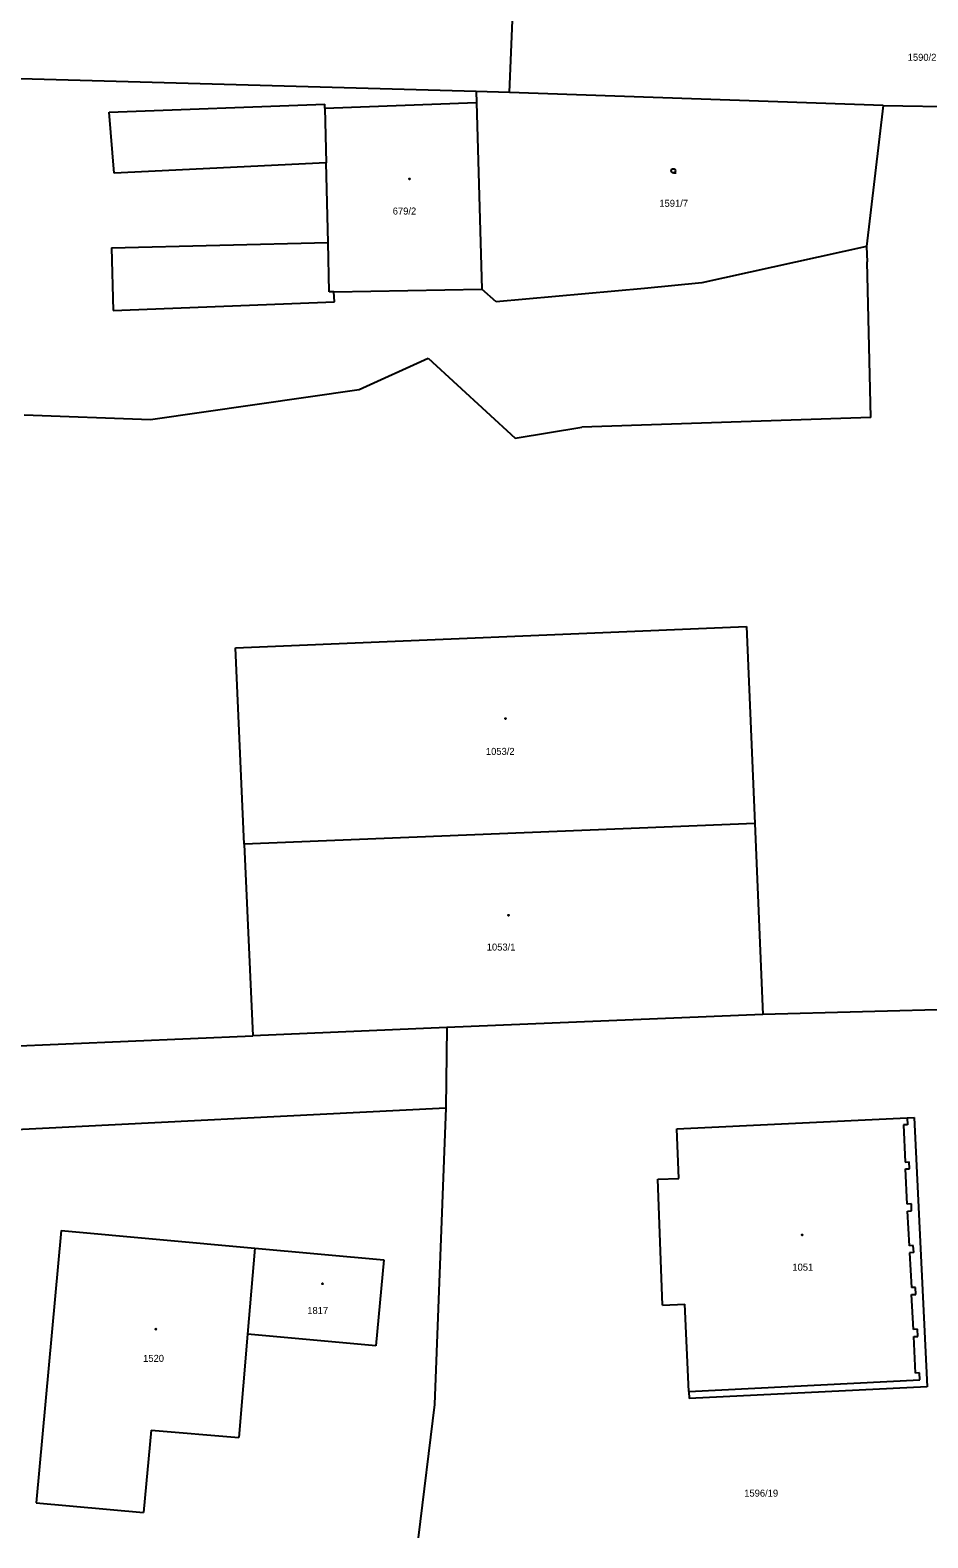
# Model space of a CAD drawing. Extents: x -866624 to -866276, y -1050208 to -1049940.
# Drawn here: x -866393.3 to -866329.4, y -1050208.1 to -1050100.7 of the extents above; entities that cross this region are included whole.
import ezdxf

# ---------------------------------------------------------------- set-up
doc = ezdxf.new("R2010")
doc.units = 0
for name, color, linetype in [('Default', 7, 'Continuous'), ('Hranice', 7, 'Continuous'), ('Hranice další', 7, 'Continuous'), ('Hranice-budov', 7, 'Continuous'), ('Parcela-pozemkova', 7, 'Continuous'), ('Parcela-stavebni', 7, 'Continuous'), ('znacky-budov', 7, 'Continuous'), ('Znacky-kultury', 7, 'Continuous')]:
    doc.layers.add(name, color=color, linetype=linetype)

# ---------------------------------------------------------------- blocks, each defined once
blk = doc.blocks.new('p_zahr')
at = {"layer": 'Default'}
blk.add_line((0, -0.75), (0.99, -0.75), dxfattribs=at)
blk.add_circle((0, 0), 0.75, dxfattribs=at)
blk = doc.blocks.new('s_zdena')
at = {"layer": 'Default'}
blk.add_circle((0, 0), 0.175, dxfattribs=at)
for start, end in [(0, 180), (180, 0)]:
    blk.add_arc((0, 0), 0.0875, start, end, dxfattribs=at)

msp = doc.modelspace()

# ---------------------------------------------------------------- linework, layer by layer
at = {"layer": 'Hranice'}
for p, q in [((-866359.18, -1050105.1), (-866358.8, -1050095.64)), ((-866361.55, -1050105.03), (-866399.74, -1050103.97)), ((-866359.18, -1050105.1), (-866361.55, -1050105.03)), ((-866361.55, -1050105.03), (-866361.53, -1050105.82)), ((-866332.54, -1050106.03), (-866359.18, -1050105.1)), ((-866387.7, -1050106.5), (-866372.34, -1050105.95)), ((-866387.36, -1050110.85), (-866387.7, -1050106.5)), ((-866372.33, -1050106.22), (-866372.34, -1050105.95)), ((-866372.33, -1050106.22), (-866361.53, -1050105.82)), ((-866361.53, -1050105.82), (-866361.15, -1050119.13)), ((-866332.54, -1050106.03), (-866333.74, -1050116.1)), ((-866332.54, -1050106.03), (-866295.74, -1050106.73)), ((-866372.25, -1050110.12), (-866387.36, -1050110.85)), ((-866372.11, -1050115.81), (-866372.25, -1050110.12)), ((-866387.54, -1050116.19), (-866372.11, -1050115.81)), ((-866387.54, -1050116.19), (-866387.43, -1050120.65)), ((-866333.74, -1050116.1), (-866345.48, -1050118.69)), ((-866333.74, -1050116.1), (-866333.7, -1050117.18)), ((-866333.42, -1050128.28), (-866333.7, -1050117.18)), ((-866371.69, -1050119.32), (-866361.15, -1050119.13)), ((-866371.66, -1050120.04), (-866371.69, -1050119.32)), ((-866360.13, -1050120.04), (-866361.15, -1050119.13)), ((-866349.55, -1050119.09), (-866360.13, -1050120.04)), ((-866345.48, -1050118.69), (-866349.55, -1050119.09)), ((-866387.43, -1050120.65), (-866371.66, -1050120.04)), ((-866369.89, -1050126.29), (-866364.98, -1050124.04)), ((-866364.98, -1050124.04), (-866358.77, -1050129.74)), ((-866384.76, -1050128.41), (-866369.89, -1050126.29)), ((-866393.77, -1050128.08), (-866384.76, -1050128.41)), ((-866333.42, -1050128.28), (-866354.03, -1050128.97)), ((-866358.77, -1050129.74), (-866354.03, -1050128.97)), ((-866378.7, -1050144.71), (-866342.28, -1050143.18)), ((-866342.28, -1050143.18), (-866341.69, -1050157.21)), ((-866378.08, -1050158.7), (-866378.7, -1050144.71)), ((-866341.69, -1050157.21), (-866378.08, -1050158.7)), ((-866341.69, -1050157.21), (-866341.12, -1050170.83)), ((-866378.08, -1050158.7), (-866377.47, -1050172.35)), ((-866341.12, -1050170.83), (-866363.65, -1050171.77)), ((-866326.22, -1050170.44), (-866341.12, -1050170.83)), ((-866395.24, -1050173.11), (-866377.47, -1050172.35)), ((-866363.65, -1050171.77), (-866377.47, -1050172.35)), ((-866363.65, -1050171.77), (-866363.72, -1050177.49)), ((-866400.49, -1050179.35), (-866363.72, -1050177.49)), ((-866363.72, -1050177.49), (-866364.52, -1050198.63)), ((-866347.26, -1050179), (-866330.84, -1050178.2)), ((-866330.84, -1050178.2), (-866330.34, -1050178.18)), ((-866330.34, -1050178.18), (-866329.43, -1050196.87)), ((-866347.1, -1050182.52), (-866347.26, -1050179)), ((-866348.6, -1050182.57), (-866347.1, -1050182.52)), ((-866348.27, -1050191.55), (-866348.6, -1050182.57)), ((-866391.14, -1050186.23), (-866392.91, -1050205.65)), ((-866391.14, -1050186.23), (-866377.33, -1050187.49)), ((-866377.33, -1050187.49), (-866377.84, -1050193.63)), ((-866377.33, -1050187.49), (-866368.14, -1050188.33)), ((-866368.14, -1050188.33), (-866368.7, -1050194.46)), ((-866348.27, -1050191.55), (-866346.69, -1050191.49)), ((-866346.41, -1050197.72), (-866346.69, -1050191.49)), ((-866377.84, -1050193.63), (-866378.46, -1050200.99)), ((-866368.7, -1050194.46), (-866377.84, -1050193.63)), ((-866329.43, -1050196.87), (-866329.41, -1050197.37)), ((-866346.41, -1050197.72), (-866346.38, -1050198.22)), ((-866329.41, -1050197.37), (-866346.38, -1050198.22)), ((-866364.52, -1050198.63), (-866365.69, -1050208.15)), ((-866384.71, -1050200.47), (-866385.26, -1050206.34)), ((-866384.71, -1050200.47), (-866378.46, -1050200.99)), ((-866392.91, -1050205.65), (-866385.26, -1050206.34))]:
    msp.add_line(p, q, dxfattribs=at)
at = {"layer": 'Hranice další'}
for p, q in [((-866372.33, -1050106.22), (-866372.25, -1050110.12)), ((-866372.02, -1050119.33), (-866372.11, -1050115.81)), ((-866371.69, -1050119.32), (-866372.02, -1050119.33)), ((-866330.82, -1050178.7), (-866331.1, -1050178.71)), ((-866331.1, -1050178.71), (-866330.98, -1050181.36)), ((-866330.84, -1050178.2), (-866330.82, -1050178.7)), ((-866330.98, -1050181.36), (-866330.69, -1050181.34)), ((-866330.95, -1050181.85), (-866330.66, -1050181.84)), ((-866330.83, -1050184.35), (-866330.95, -1050181.85)), ((-866330.66, -1050181.84), (-866330.69, -1050181.34)), ((-866330.54, -1050184.33), (-866330.83, -1050184.35)), ((-866330.81, -1050184.85), (-866330.52, -1050184.83)), ((-866330.68, -1050187.32), (-866330.81, -1050184.85)), ((-866330.52, -1050184.83), (-866330.54, -1050184.33)), ((-866330.4, -1050187.31), (-866330.68, -1050187.32)), ((-866330.37, -1050187.81), (-866330.4, -1050187.31)), ((-866330.37, -1050187.81), (-866330.66, -1050187.83)), ((-866330.66, -1050187.83), (-866330.54, -1050190.3)), ((-866330.25, -1050190.29), (-866330.54, -1050190.3)), ((-866330.23, -1050190.79), (-866330.25, -1050190.29)), ((-866330.52, -1050190.8), (-866330.23, -1050190.79)), ((-866330.39, -1050193.29), (-866330.52, -1050190.8)), ((-866330.11, -1050193.27), (-866330.39, -1050193.29)), ((-866330.37, -1050193.8), (-866330.08, -1050193.79)), ((-866330.24, -1050196.41), (-866330.37, -1050193.8)), ((-866330.08, -1050193.79), (-866330.11, -1050193.27)), ((-866346.41, -1050197.72), (-866329.93, -1050196.89)), ((-866329.95, -1050196.39), (-866330.24, -1050196.41)), ((-866329.93, -1050196.89), (-866329.95, -1050196.39))]:
    msp.add_line(p, q, dxfattribs=at)
at = {"layer": 'Hranice-budov'}
for p, q in [((-866372.33, -1050106.22), (-866361.53, -1050105.82)), ((-866372.33, -1050106.22), (-866372.25, -1050110.12)), ((-866361.53, -1050105.82), (-866361.15, -1050119.13)), ((-866372.11, -1050115.81), (-866372.25, -1050110.12)), ((-866372.02, -1050119.33), (-866372.11, -1050115.81)), ((-866371.69, -1050119.32), (-866372.02, -1050119.33)), ((-866371.69, -1050119.32), (-866361.15, -1050119.13)), ((-866378.7, -1050144.71), (-866342.28, -1050143.18)), ((-866342.28, -1050143.18), (-866341.69, -1050157.21)), ((-866378.08, -1050158.7), (-866378.7, -1050144.71)), ((-866341.69, -1050157.21), (-866378.08, -1050158.7)), ((-866341.69, -1050157.21), (-866378.08, -1050158.7)), ((-866341.69, -1050157.21), (-866341.12, -1050170.83)), ((-866378.08, -1050158.7), (-866377.47, -1050172.35)), ((-866341.12, -1050170.83), (-866363.65, -1050171.77)), ((-866363.65, -1050171.77), (-866377.47, -1050172.35)), ((-866347.26, -1050179), (-866330.84, -1050178.2)), ((-866330.82, -1050178.7), (-866331.1, -1050178.71)), ((-866331.1, -1050178.71), (-866330.98, -1050181.36)), ((-866330.84, -1050178.2), (-866330.82, -1050178.7)), ((-866347.1, -1050182.52), (-866347.26, -1050179)), ((-866330.98, -1050181.36), (-866330.69, -1050181.34)), ((-866330.95, -1050181.85), (-866330.66, -1050181.84)), ((-866330.83, -1050184.35), (-866330.95, -1050181.85)), ((-866330.66, -1050181.84), (-866330.69, -1050181.34)), ((-866348.6, -1050182.57), (-866347.1, -1050182.52)), ((-866348.27, -1050191.55), (-866348.6, -1050182.57)), ((-866330.54, -1050184.33), (-866330.83, -1050184.35)), ((-866330.81, -1050184.85), (-866330.52, -1050184.83)), ((-866330.68, -1050187.32), (-866330.81, -1050184.85)), ((-866330.52, -1050184.83), (-866330.54, -1050184.33)), ((-866391.14, -1050186.23), (-866392.91, -1050205.65)), ((-866391.14, -1050186.23), (-866377.33, -1050187.49)), ((-866330.4, -1050187.31), (-866330.68, -1050187.32)), ((-866330.37, -1050187.81), (-866330.4, -1050187.31)), ((-866377.33, -1050187.49), (-866377.84, -1050193.63)), ((-866377.33, -1050187.49), (-866377.84, -1050193.63)), ((-866377.33, -1050187.49), (-866368.14, -1050188.33)), ((-866368.14, -1050188.33), (-866368.7, -1050194.46)), ((-866330.37, -1050187.81), (-866330.66, -1050187.83)), ((-866330.66, -1050187.83), (-866330.54, -1050190.3)), ((-866330.25, -1050190.29), (-866330.54, -1050190.3)), ((-866330.23, -1050190.79), (-866330.25, -1050190.29)), ((-866348.27, -1050191.55), (-866346.69, -1050191.49)), ((-866346.41, -1050197.72), (-866346.69, -1050191.49)), ((-866330.52, -1050190.8), (-866330.23, -1050190.79)), ((-866330.39, -1050193.29), (-866330.52, -1050190.8)), ((-866377.84, -1050193.63), (-866378.46, -1050200.99)), ((-866368.7, -1050194.46), (-866377.84, -1050193.63)), ((-866330.11, -1050193.27), (-866330.39, -1050193.29)), ((-866330.37, -1050193.8), (-866330.08, -1050193.79)), ((-866330.24, -1050196.41), (-866330.37, -1050193.8)), ((-866330.08, -1050193.79), (-866330.11, -1050193.27)), ((-866346.41, -1050197.72), (-866329.93, -1050196.89)), ((-866329.95, -1050196.39), (-866330.24, -1050196.41)), ((-866329.93, -1050196.89), (-866329.95, -1050196.39)), ((-866384.71, -1050200.47), (-866385.26, -1050206.34)), ((-866384.71, -1050200.47), (-866378.46, -1050200.99)), ((-866392.91, -1050205.65), (-866385.26, -1050206.34))]:
    msp.add_line(p, q, dxfattribs=at)

# ---------------------------------------------------------------- block references
at = {"layer": 'znacky-budov', "xscale": 0.2, "yscale": 0.20000000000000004}
for p in [(-866366.3, -1050111.27), (-866359.46, -1050149.74), (-866359.26, -1050163.76), (-866338.32, -1050186.55), (-866372.5, -1050190.03), (-866384.38, -1050193.27)]:
    msp.add_blockref('s_zdena', p, dxfattribs=at)
at = {"layer": 'Znacky-kultury', "xscale": 0.2, "yscale": 0.20000000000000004}
msp.add_blockref('p_zahr', (-866347.5, -1050110.69), dxfattribs=at)

# ---------------------------------------------------------------- texts
at = {"layer": 'Parcela-pozemkova'}
for s, p in [('1590/2', (-866330.8, -1050102.85)), ('1591/7', (-866348.5, -1050113.26)), ('1596/19', (-866342.45, -1050205.21))]:
    msp.add_text(s, height=0.5, dxfattribs=at).set_placement(p)
at = {"layer": 'Parcela-stavebni'}
for s, p in [('679/2', (-866367.5, -1050113.81)), ('1053/2', (-866360.86, -1050152.33)), ('1053/1', (-866360.8, -1050166.28)), ('1051', (-866339.02, -1050189.1)), ('1817', (-866373.59, -1050192.19)), ('1520', (-866385.29, -1050195.6))]:
    msp.add_text(s, height=0.5, dxfattribs=at).set_placement(p)

doc.saveas('drawing.dxf')
